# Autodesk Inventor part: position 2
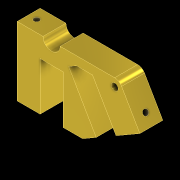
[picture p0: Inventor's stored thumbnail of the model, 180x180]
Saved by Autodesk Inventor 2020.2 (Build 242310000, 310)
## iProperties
Category: 2
Manager: PART
Company: 10
Created: 2020-10
Part Number: position 2
Material: Generic
Document SubType Name: Modeling
Designer: Apardo
Density: 1 g/cm^3
Appearance: Metal 2400F Hot
Vendor: 2
Description: POSITION 2
Project: PLATE ROLLING MACHINE
Cost Center: 1
Engineer: STEEL C45
Stock Number: 1.6
Engr Approved By: D. JAEGER
Author: Apardo
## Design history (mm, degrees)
sketch "Sketch1"
  geometry: L1 (-28.5, -30)-(-28.5, 30); L2 (62.562, 26.5)-(78.512, -1.126); L3 (40.407, -23.126)-(16.407, 18.444); L4 (16.407, 18.444)-(23.335, 22.444); L5 (23.335, 22.444)-(37.191, 22.444); L6 (37.191, 22.444)-(57.727, -13.126); L7 (-28.5, 30)-(-6, 30); L8 (9, 30)-(56.5, 30); L9 (-8.5, -30)-(-8.5, 12); L10 (-8.5, 12)-(11.5, 12); L11 (11.5, 12)-(11.5, -30); L12 (78.512, -1.126)-(57.727, -13.126); L13 (40.407, -23.126)-(28.5, -30); L14 (28.5, -30)-(11.5, -30); L15 (-8.5, -30)-(-28.5, -30); L16 (4, 22.5)-(-3, 22.5); A1 r 7 centre (56.5, 23) between (62.562, 26.5) and (56.5, 30); A2 r 7.5 centre (1.5, 30) between (-6, 30) and (9, 30); 2 further points
  constraints: 32 end point, 14 perpendicular, 4 point on circle, 4 tangent, 3 horizontal, 2 centre point, 2 collinear, 1 midpoint, 1 vertical, 1 vertical alignment
  dimensions: "d0" = 60 distance of L1.start L1.end; "d1" = 57 distance of L13.end L1.start; "d3" = 7 radius of A1; "d4" = 85 distance from line of A1.centre L1; "d6" = 28.5 distance from line of point (0, 0) L1 (= 0.5 x d1); "d7" = 60 deg angle of L5 L6; "d8" = 20 distance between parallel lines of L6 L3; "d10" = 48 distance of L3.start L3.end; "d11" = 15 diameter of A2; "d12" = 30 distance from line of A2.centre L1; "d13" = 20 distance between parallel lines of L11 L9; "d14" = 42 distance of L9.start L9.end; "d15" = 30 distance from line of L7 point (0, 0) (= 0.5 x d0); "d16" = 30 deg angle of L14 L13; "d29" = 24 distance between parallel lines of L2 L6; "d30" = 12 distance from line of L6 L4.end; "d90" = 7.5 distance between parallel lines of L16 L7
extrude "Extrusion1" new body sketch "Sketch1" stored distance "d17" = 20; taper "d18" = 0 deg
sketch "Sketch2"
  geometry: A1 r 7 centre (56.5, 23) between (62.562, 26.5) and (56.5, 30) reference; 2 further points
  constraints: 1 coincident
hole "Hole1" sketch "Sketch2" at (56.5, 23) diameter "d19" = 6.02; stored, may be unused: countersink angle "d23" = 90 deg, drill point angle "d25" = 118 deg; dims "d20" = 6, "d21" = 10, "d22" = 2, "d24" = 8
sketch "Sketch3"
  geometry: L1 (22.5, 0)-(37.5, 0) reference; 6 further points
  constraints: 2 horizontal alignment, 1 midpoint
  dimensions: "d26" = 30 distance of point (45, -10) point (15, -10); "d31" = 15 horizontal distance of point (30, 0) point (15, -10) (= 0.5 x d26)
sketch "Sketch4"
  geometry: L1 (20, 0)-(20, 20) reference; L2 (0, 0)-(0, 20) reference; L3 (0, 10)-(20, 10); 4 further points
  constraints: 3 midpoint, 2 end point, 2 horizontal alignment
  dimensions: "d33" = 30 distance of point (25, 10) point (-5, 10); "d34" = 15 distance of point (25, 10) point (10, 10) (= 0.5 x d33)
hole "Hole2" sketch "Sketch4" diameter "d35" = 4.134; stored, may be unused: countersink angle "d39" = 90 deg, drill point angle "d41" = 118 deg; dims "d36" = 13, "d37" = 10, "d38" = 2, "d40" = 13
hole "Hole3" sketch "Sketch4" diameter "d42" = 4.134; stored, may be unused: countersink angle "d46" = 90 deg, drill point angle "d48" = 118 deg; dims "d43" = 13, "d44" = 10, "d45" = 2, "d47" = 13
hole "Hole4" sketch "Sketch3" diameter "d49" = 4.134; stored, may be unused: countersink angle "d53" = 90 deg, drill point angle "d55" = 118 deg; dims "d50" = 13, "d51" = 10, "d52" = 2, "d54" = 13
hole "Hole5" sketch "Sketch3" diameter "d56" = 4.134; stored, may be unused: countersink angle "d60" = 90 deg, drill point angle "d62" = 118 deg; dims "d57" = 13, "d58" = 10, "d59" = 2, "d61" = 13
sketch "Sketch5"
  geometry: L1 (-20, 0)-(0, 0) reference; 3 further points
  constraints: 2 vertical alignment
  dimensions: "d63" = 8 distance from line of L1 point (-10, 8); "d64" = 35 distance of point (-10, 43) point (-10, 8)
hole "Hole6" sketch "Sketch5" at (-10, 8), (-10, 43) diameter "d65" = 4.917; stored, may be unused: countersink angle "d69" = 90 deg, drill point angle "d71" = 118 deg; dims "d66" = 10, "d67" = 10, "d68" = 2, "d70" = 10
sketch "Sketch6"
  geometry: L1 (0, 0)-(0, 20) reference; L2 (22.5, 0)-(0, 0) reference; 2 further points
  dimensions: "d72" = 7 distance from line of L1 point (7, 10); "d80" = 10 distance from line of L2 point (7, 10)
hole "Hole7" sketch "Sketch6" at (7, 10) diameter "d73" = 4.917; stored, may be unused: countersink angle "d77" = 90 deg, drill point angle "d79" = 118 deg; dims "d74" = 12, "d75" = 10, "d76" = 2, "d78" = 12
sketch "Sketch7"
  geometry: L1 (20, 0)-(20, -31.899) reference; L2 (20, -31.899)-(0, -31.899) reference; 2 further points
  dimensions: "d81" = 10 distance from line of L1 point (10, -22.069); "d82" = 9.83 distance from line of L2 point (10, -22.069)
hole "Hole8" sketch "Sketch7" at (10, -22.069) diameter "d83" = 4.917; stored, may be unused: countersink angle "d87" = 90 deg, drill point angle "d89" = 118 deg; dims "d84" = 13, "d85" = 4, "d86" = 2, "d88" = 13
body "Solid1"
other parameters: "d2" = 30 deg
